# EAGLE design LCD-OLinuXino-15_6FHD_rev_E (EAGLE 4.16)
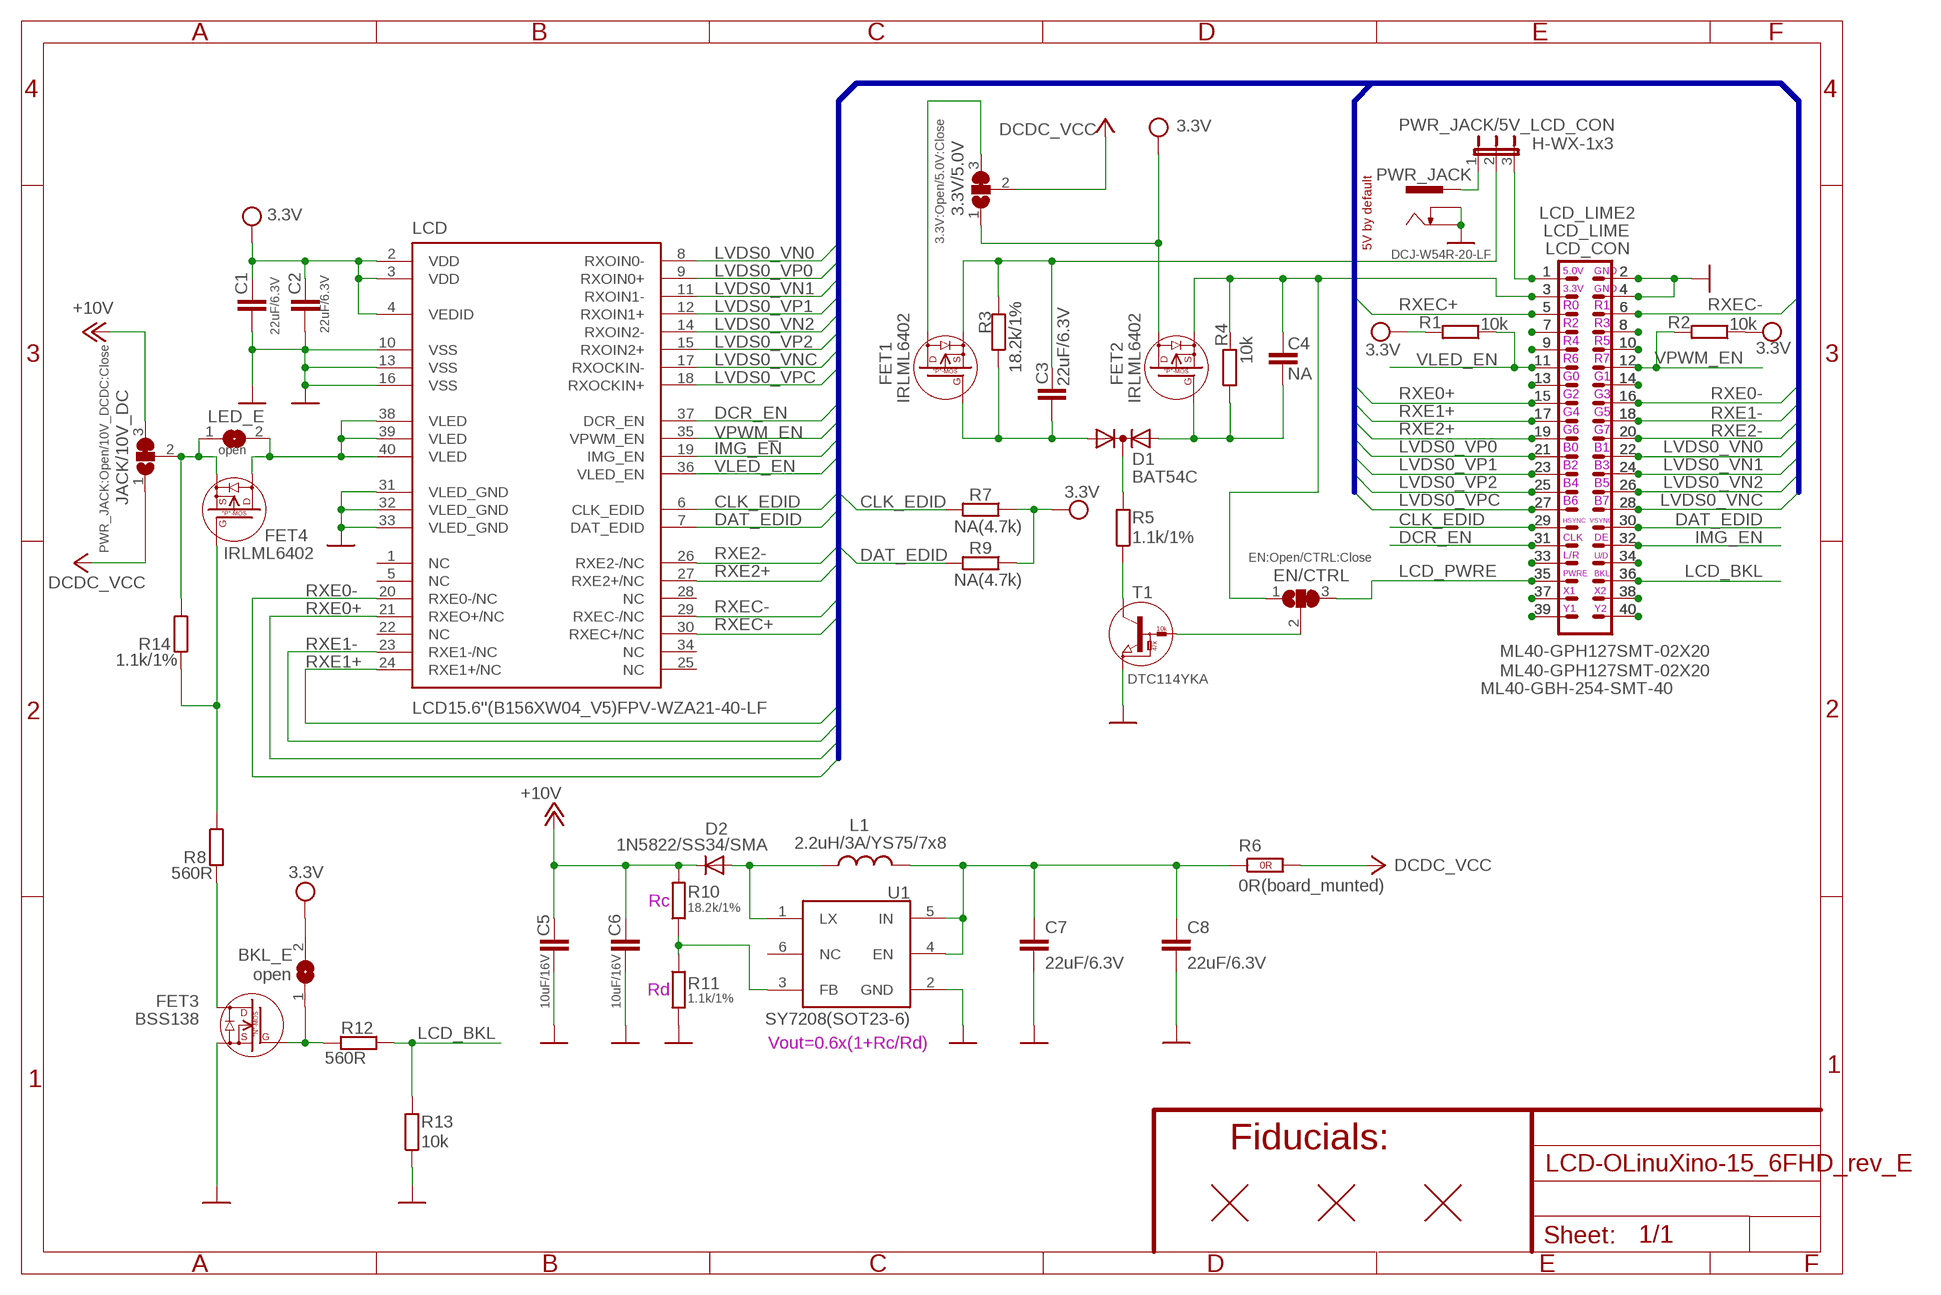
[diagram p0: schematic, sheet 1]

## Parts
3.3V/5.0V  3.3V:Open/5.0V:Close  SJ2W5  [SJ_2_SMALL_23_TIED]
BKL_E  open  SJSJ_1_THE_SMALLEST  [SJ_1_THE_SMALLEST]
C1  22uF/6.3V  C-EUC0603_DWS  [C0603_DWS]
C2  22uF/6.3V  C-EUC0603_DWS  [C0603_DWS]
C3  22uF/6.3V  C-EUC0603_DWS  [C0603_DWS]
C4  NA  C-EUC0603_DWS  [C0603_DWS]
C5  10uF/16V  C-EUC0805_5MIL_DWS  [C0805_5MIL_DWS]
C6  10uF/16V  C-EUC0805_5MIL_DWS  [C0805_5MIL_DWS]
C7  22uF/6.3V  C-EUC0603_DWS  [C0603_DWS]
C8  22uF/6.3V  C-EUC0603_DWS  [C0603_DWS]
D1  BAT54C  DIODE_AC-CA_  [SOT23C]
D2  1N5822/SS34/SMA  D-MLL-41  [MELF-MLL41]
EN/CTRL  EN:Open/CTRL:Close  SJ2W5  [SJ_2_SMALL_23_TIED]
FET1  IRLML6402  P-MOS+DIODIRLML6402  [SOT23]
FET2  IRLML6402  P-MOS+DIODIRLML6402  [SOT23]
FET3  BSS138  N-MOS+DIODBSS138(SOT23-3)  [SOT23]
FET4  IRLML6402  P-MOS+DIODIRLML6402  [SOT23]
JACK/10V_DC  PWR_JACK:Open/10V_DCDC:Close  SJ2W3  [SJ_2_SMALL]
L1  2.2uH/3A/YS75/7x8  LLQH88PN100M38  [8X8MM_3131]
LCD  LCD15.6''(B156XW04_V5)FPV-WZA21-40-LF  [LCD_15.6'']
LCD_CON  ML40-GBH-254-SMT-40  [ML40-MALE(GBH-254-SMT-40)]
LCD_LIME  ML40-GPH127SMT-02X20  ML40YA-V36P-2X20-LF  [YA-V36P-2X20-LF]
LCD_LIME2  ML40-GPH127SMT-02X20  ML40-GPH127SMT-02X20(PA-V16X-2X20-LF)  [GPH127SMT-02X20(PA-V16X-2X20-LF)]
LED_E  open  SJSJ_1_THE_SMALLEST  [SJ_1_THE_SMALLEST]
PWR_JACK  DCJ-W54R-20-LF  PWR-JAKDCJ-W  [PWR-JACK-SMD]
PWR_JACK/5V_LCD_CON  H-WX-1x3  JP2EHN1X3-SMD  [HN1X3-SMD]
R1  10k  R-EU_R0603_5MIL_DWS  [R0603_5MIL_DWS]
R2  10k  R-EU_R0603_5MIL_DWS  [R0603_5MIL_DWS]
R3  18.2k/1%  R-EU_R0603_5MIL_DWS  [R0603_5MIL_DWS]
R4  10k  R-EU_R0603_5MIL_DWS  [R0603_5MIL_DWS]
R5  1.1k/1%  R-EU_R0603_5MIL_DWS  [R0603_5MIL_DWS]
R6  0R(board_munted)  R_0R0R(NA)  [0603_0R]
R7  NA(4.7k)  R-EU_R0603_5MIL_DWS  [R0603_5MIL_DWS]
R8  560R  R-EU_R0603_5MIL_DWS  [R0603_5MIL_DWS]
R9  NA(4.7k)  R-EU_R0603_5MIL_DWS  [R0603_5MIL_DWS]
R10  18.2k/1%  R-EU_R0603_5MIL_DWS  [R0603_5MIL_DWS]
R11  1.1k/1%  R-EU_R0603_5MIL_DWS  [R0603_5MIL_DWS]
R12  560R  R-EU_R0603_5MIL_DWS  [R0603_5MIL_DWS]
R13  10k  R-EU_R0603_5MIL_DWS  [R0603_5MIL_DWS]
R14  1.1k/1%  R-EU_R0603_5MIL_DWS  [R0603_5MIL_DWS]
T1  DTC114YKA  DIGITAL_TRANSISTORS-NPNDTC114YKA  [SOT-23]
U1  SY7208(SOT23-6)  SY7208  [SOT23-6]
U$1  FIDUCIAL  [FIDUCIAL-1X3]
U$2  FIDUCIAL  [FIDUCIAL-1X3]
U$3  FIDUCIAL  [FIDUCIAL-1X3]

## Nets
3.3VDC [pwr]: C4.1 EN/CTRL.1 FET2.2(S) LCD_CON.3 LCD_LIME2.3 LCD_LIME.3 R4.2
5VDC: C3.1 FET1.2(S) PWR_JACK/5V_LCD_CON.2 R3.2
+5V: 3.3V/5.0V.2 JACK/10V_DC.1 R6.2(1.2) ; supply symbol labelled DCDC_VCC
+12V [pwr]: C5.1 C6.1 D2.1(C) JACK/10V_DC.3 R10.2 ; supply symbol labelled +10V
CLK_EDID: LCD.6(CLK_EDID) LCD_CON.29 LCD_LIME2.29 LCD_LIME.29 R7.2
DAT_EDID: LCD.7(DAT_EDID) LCD_CON.30 LCD_LIME2.30 LCD_LIME.30 R9.2
DCR_EN: LCD.37(DCR_EN) LCD_CON.31 LCD_LIME2.31 LCD_LIME.31
GND [pwr]: C1.2 C2.2 C5.2 C6.2 C7.2 C8.2 FET3.2(S) LCD.10(VSS) LCD.13(VSS) LCD.16(VSS) LCD.31(VLED_GND) LCD.32(VLED_GND) LCD.33(VLED_GND) LCD_CON.2 LCD_CON.4 LCD_LIME2.2 LCD_LIME2.4 LCD_LIME.2 LCD_LIME.4 PWR_JACK.2(-) PWR_JACK.3(--) R11.2 R13.1 T1.2(E) U1.2(GND)
IMG_EN: LCD.19(IMG_EN) LCD_CON.32 LCD_LIME2.32 LCD_LIME.32
LCD_BKL: LCD_CON.36 LCD_LIME2.36 LCD_LIME.36 R12.1 R13.2
LCD_PWRE: EN/CTRL.3 LCD_CON.35 LCD_LIME2.35 LCD_LIME.35
LVDS0_VN0: LCD.8(RXOIN0-) LCD_CON.22 LCD_LIME2.22 LCD_LIME.22
LVDS0_VN1: LCD.11(RXOIN1-) LCD_CON.24 LCD_LIME2.24 LCD_LIME.24
LVDS0_VN2: LCD.14(RXOIN2-) LCD_CON.26 LCD_LIME2.26 LCD_LIME.26
LVDS0_VNC: LCD.17(RXOCKIN-) LCD_CON.28 LCD_LIME2.28 LCD_LIME.28
LVDS0_VP0: LCD.9(RXOIN0+) LCD_CON.21 LCD_LIME2.21 LCD_LIME.21
LVDS0_VP1: LCD.12(RXOIN1+) LCD_CON.23 LCD_LIME2.23 LCD_LIME.23
LVDS0_VP2: LCD.15(RXOIN2+) LCD_CON.25 LCD_LIME2.25 LCD_LIME.25
LVDS0_VPC: LCD.18(RXOCKIN+) LCD_CON.27 LCD_LIME2.27 LCD_LIME.27
N$1: 3.3V/5.0V.3 FET1.3(D)
N$2 [pwr]: FET4.2(S) JACK/10V_DC.2 LED_E.1 R14.1
N$3 [pwr]: FET4.3(D) LCD.38(VLED) LCD.39(VLED) LCD.40(VLED) LED_E.2
N$4: BKL_E.1 FET3.1(G) R12.2
N$5: LCD_CON.7 LCD_LIME2.7 LCD_LIME.7
N$6: LCD_CON.9 LCD_LIME2.9 LCD_LIME.9
N$7: LCD_CON.13 LCD_LIME2.13 LCD_LIME.13
N$8: C4.2 D1.1(A1) FET2.1(G) R4.1
N$9: C3.2 D1.2(A2) FET1.1(G) R3.1
N$10: LCD_CON.33 LCD_LIME2.33 LCD_LIME.33
N$11: R5.1 T1.3(C)
N$12: LCD_CON.37 LCD_LIME2.37 LCD_LIME.37
N$13: LCD_CON.39 LCD_LIME2.39 LCD_LIME.39
N$14: LCD_CON.8 LCD_LIME2.8 LCD_LIME.8
N$15: LCD_CON.10 LCD_LIME2.10 LCD_LIME.10
N$16: EN/CTRL.2 T1.1(B)
N$17: LCD_CON.14 LCD_LIME2.14 LCD_LIME.14
N$18: LCD_CON.34 LCD_LIME2.34 LCD_LIME.34
N$19: D1.3(K) R5.2
N$20: LCD_CON.1 LCD_LIME2.1 LCD_LIME.1 PWR_JACK/5V_LCD_CON.3
N$21: LCD_CON.38 LCD_LIME2.38 LCD_LIME.38
N$22 [pwr]: PWR_JACK.1(+) PWR_JACK/5V_LCD_CON.1
N$23: LCD_CON.40 LCD_LIME2.40 LCD_LIME.40
N$24: C7.1 C8.1 L1.2 R6.1(1.1) U1.4(EN) U1.5(IN)
N$25: FET4.1(G) R8.1 R14.2
N$26: FET3.3(D) R8.2
N$123: D2.2(A) L1.1 U1.1(LX)
N$126: R10.1 R11.1 U1.3(FB)
RXE0+: LCD.21(RXEO+/NC) LCD_CON.15 LCD_LIME2.15 LCD_LIME.15
RXE0-: LCD.20(RXE0-/NC) LCD_CON.16 LCD_LIME2.16 LCD_LIME.16
RXE1+: LCD.24(RXE1+/NC) LCD_CON.17 LCD_LIME2.17 LCD_LIME.17
RXE1-: LCD.23(RXE1-/NC) LCD_CON.18 LCD_LIME2.18 LCD_LIME.18
RXE2+: LCD.27(RXE2+/NC) LCD_CON.19 LCD_LIME2.19 LCD_LIME.19
RXE2-: LCD.26(RXE2-/NC) LCD_CON.20 LCD_LIME2.20 LCD_LIME.20
RXEC+: LCD.30(RXEC+/NC) LCD_CON.5 LCD_LIME2.5 LCD_LIME.5
RXEC-: LCD.29(RXEC-/NC) LCD_CON.6 LCD_LIME2.6 LCD_LIME.6
VCC [pwr]: 3.3V/5.0V.1 BKL_E.2 C1.1 C2.1 FET2.3(D) LCD.2(VDD) LCD.3(VDD) LCD.4(VEDID) R1.2 R2.1 R7.1 R9.1 ; supply symbol labelled 3.3V
VLED_EN: LCD.36(VLED_EN) LCD_CON.11 LCD_LIME2.11 LCD_LIME.11 R1.1
VPWM_EN: LCD.35(VPWM_EN) LCD_CON.12 LCD_LIME2.12 LCD_LIME.12 R2.2
Unconnected: LCD.1(NC) LCD.5(NC) LCD.22(NC) LCD.25(NC) LCD.28(NC) LCD.34(NC) U1.6(NC)

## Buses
LVDS0_VP[0..2],LVDS0_VN[0..2],LVDS0_VPC,LVDS0_VNC,CLK_EDID,DAT_EDID,DCR_EN,IMG_EN,VPWM_EN,VLED_EN,RXE0-,RXE0+,RXE1-,RXE1+,RXE2-,RXE2+,RXEC-,RXEC+

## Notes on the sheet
- 5V by default
- 5.0V | GND
- 3.3V | GND
- R0 | R1
- R2 | R3
- R4 | R5
- R6 | R7
- G0 | G1
- G2 | G3
- G4 | G5
- G6 | G7
- B0 | B1
- B2 | B3
- B4 | B5
- B6 | B7
- HSYNC | VSYNC
- CLK | DE
- L/R | U/D
- PWRE | BKL
- X1 | X2
- Y1 | Y2
- Rc
- Rd
- Vout=0.6x(1+Rc/Rd)
- Fiducials:

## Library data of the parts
3.3V/5.0V EN/CTRL JACK/10V_DC = jumper:SJ2W: SMD solder JUMPER
BKL_E LED_E = jumper:SJ: SMD solder JUMPER
C1-C8 = rcl:C-EU: CAPACITOR, European symbol
D1 = semicon-smd-ipc:DIODE_AC-CA_: DUAL DIODE
D2 = semicon-smd-ipc:D-: DIODE
FET1 FET2 FET4 = Penko:P-MOS+DIOD
FET3 = Penko:N-MOS+DIOD
L1 = OLIMEX_DISCRET:L
LCD = olimex_lcd:LCD15.6''(B156XW04_V5): LCD B156XW04 V5 LCD type: Color Active Matrix Liquid Cristal Display composed of a TFT LCD panel, a driver circuit, and LED backlight system Screen format: 16x9 HD(1366x768 pixels) Number of colors: 262K colors(RGB 6-bits data driver) Pixel Pitch: 0.252x0.252mm Pixel Format: RGB Vertical Stripe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
LCD_CON LCD_LIME LCD_LIME2 = con-harting-ml:ML40: HARTING
PWR_JACK = gogo:PWR-JAK
PWR_JACK/5V_LCD_CON = jumper:JP2E: JUMPER
R1-R5 R7-R14 = rcl:R-EU_: RESISTOR, European symbol
R6 = OLIMEX_DISCRET:R_0R
T1 = OLIMEX_DISCRET:DIGITAL_TRANSISTORS-NPN: DTC114YKA Digital Transistor - NPN
U1 = OLIMEX_IC:SY7208
U$1-U$3 = SparkFunEagle-6-6-07:FIDUCIAL: Fiducial Alignment Points

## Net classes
1 pwr: width 0.254 mm, drill 0.241 mm, clearance 0.254 mm

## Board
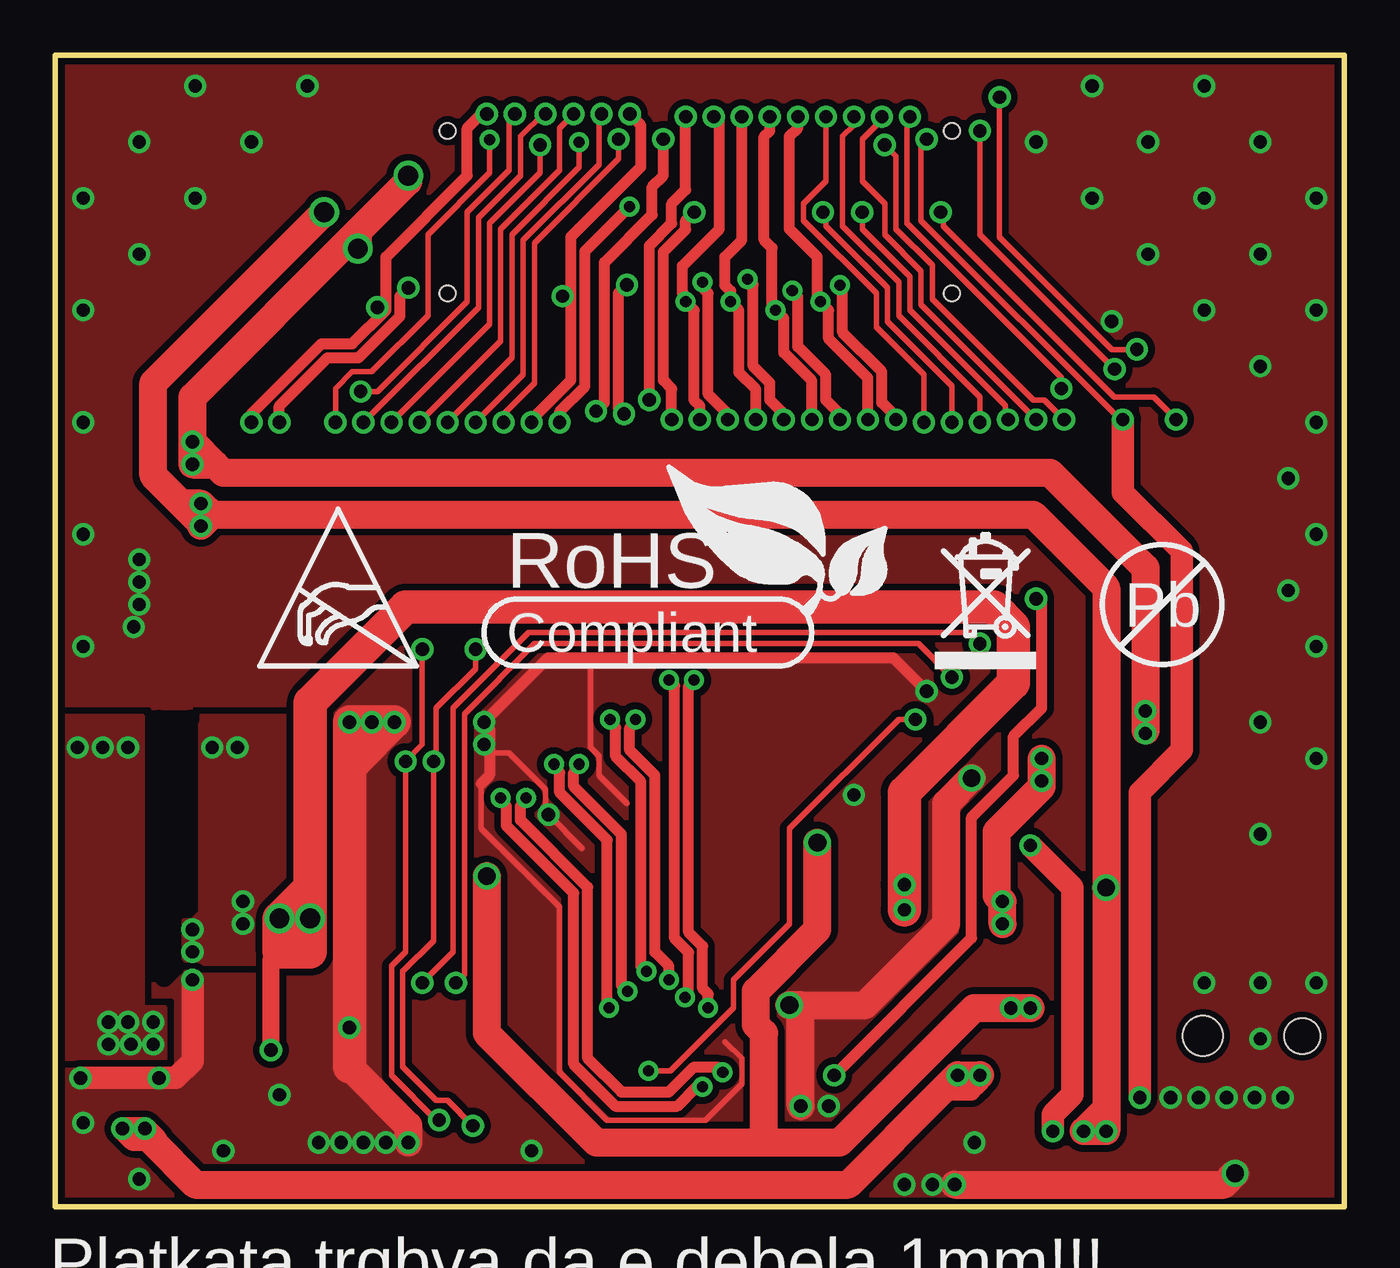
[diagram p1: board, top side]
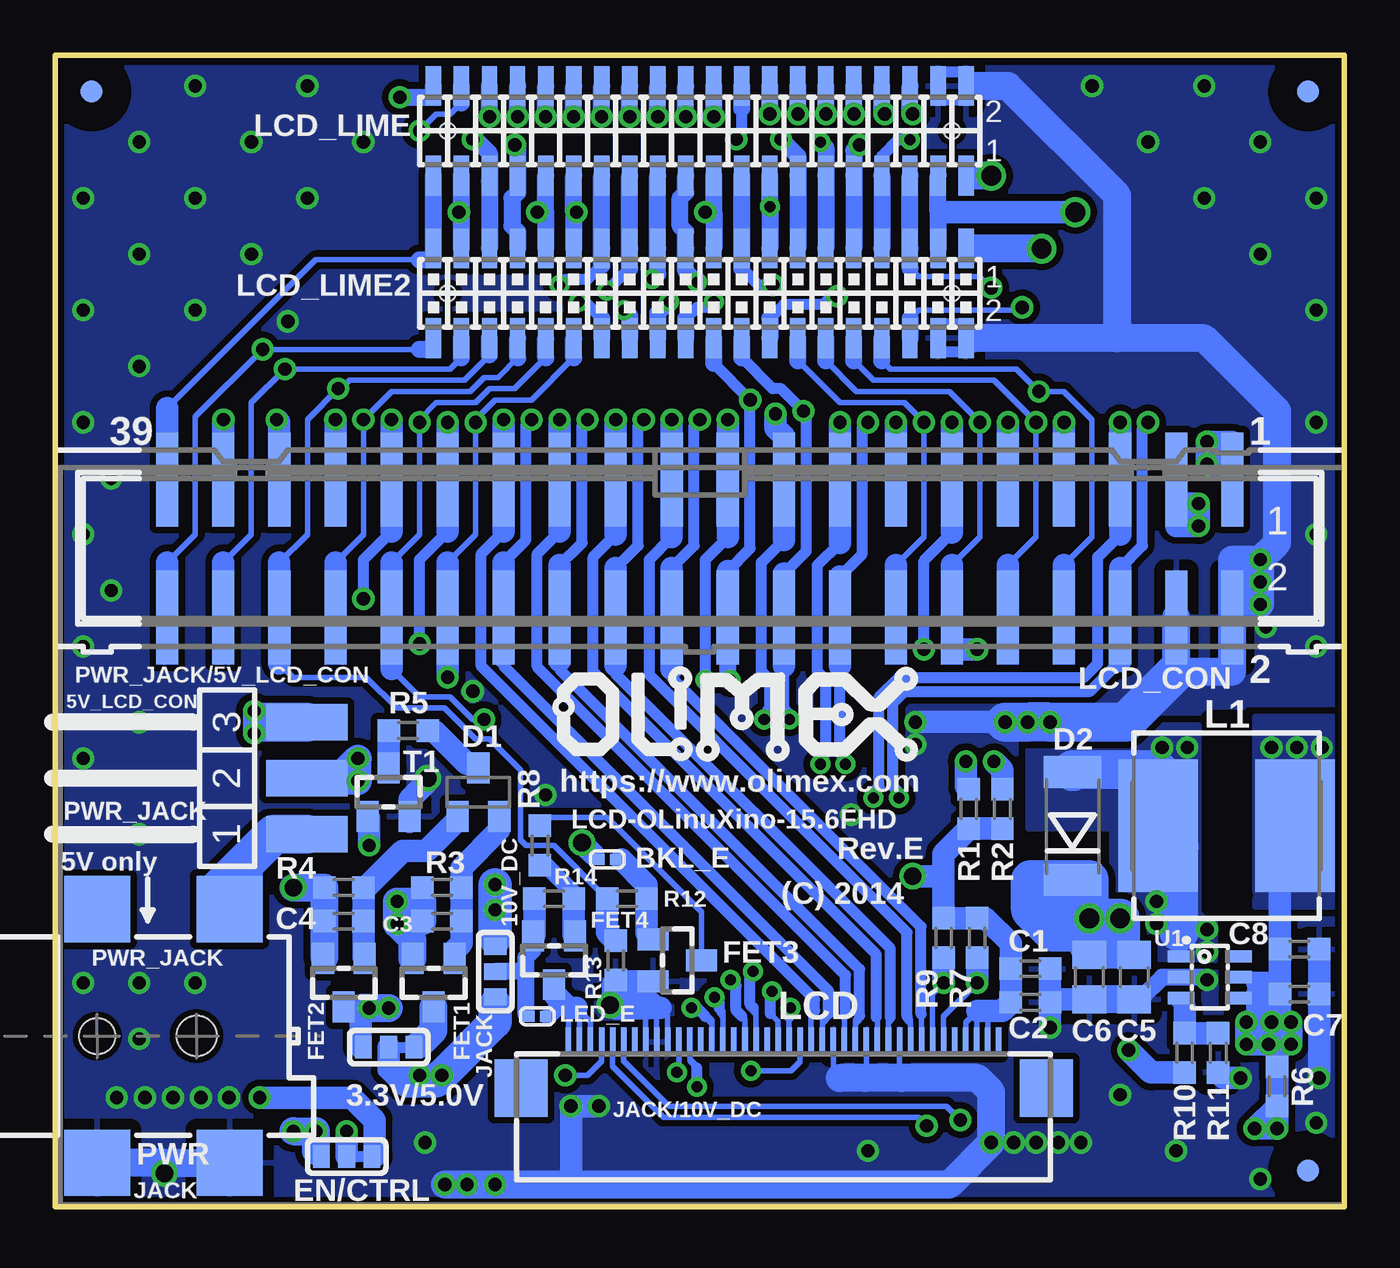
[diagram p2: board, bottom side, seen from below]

Size 58.42 x 52.2 mm. Coordinates in mm from the lower left corner, seen from the top.
Outline: 0,52.2 0,0 58.42,0 58.42,52.2 0,52.2
Copper layers (1+16): Top 0.035mm / dielectric 1mm / Bottom 0.035mm
Design rules "default": minimum track width 9.5mil, minimum drill 0.5mm, track to track 5mil, track to pad 5mil, pad to pad 5mil, via to via 5mil, smd to smd 1mil, copper to edge 10mil, drill to drill 8mil, minimum pad ring 8mil, minimum via ring 8mil, stop-mask expansion 4mil, vias tented up to drill 40mil, thermal gap 20mil
tRestrict: 3 lines
bRestrict: 2 lines

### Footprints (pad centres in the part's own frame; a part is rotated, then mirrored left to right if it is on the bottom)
SJ_2_SMALL_23_TIED = smd 0.762 x 1.016: 1 -1.143,0; 2 0,0; 3 1.143,0
SJ_1_THE_SMALLEST = smd 0.508 x 0.508: 1 -0.381,0; 2 0.381,0
C0603_DWS = smd 1.016 x 1.016: 1 -0.889,0; 2 0.889,0
C0805_5MIL_DWS = smd 1.27 x 1.524: 1 -1.016,0; 2 1.016,0
SOT23C = smd 1.4 x 1: 1 1.1,-0.95; 2 1.1,0.95; 3 -1.1,0
MELF-MLL41 = smd 1.45 x 2.6: 1 -2.445,0; 2 2.445,0
SOT23 = smd 1.4 x 1: 1 1.1,-0.95; 2 1.1,0.95; 3 -1.1,0
SJ_2_SMALL = smd 0.762 x 1.016: 1 -1.143,0; 2 0,0; 3 1.143,0
8X8MM_3131 = smd 3.6 x 6: 1 -3.1,0; 2 3.1,0
LCD_15.6'' = smd 0.25 x 1.3 bottom: 1 -67.54,31.89; 2 -67.04,31.89; 3 -66.54,31.89; 4 -66.04,31.89; 5 -65.54,31.89; 6 -65.04,31.89; 7 -64.54,31.89; 8 -64.04,31.89; 9 -63.54,31.89; 10 -63.04,31.89; 11 -62.54,31.89; 12 -62.04,31.89; 13 -61.54,31.89; 14 -61.04,31.89; 15 -60.54,31.89; 16 -60.04,31.89; 17 -59.54,31.89; 18 -59.04,31.89; 19 -58.54,31.89; 20 -58.04,31.89; 21 -57.54,31.89; 22 -57.04,31.89; 23 -56.54,31.89; 24 -56.04,31.89; 25 -55.54,31.89; 26 -55.04,31.89; 27 -54.54,31.89; 28 -54.04,31.89; 29 -53.54,31.89; 30 -53.04,31.89; 31 -52.54,31.89; 32 -52.04,31.89; 33 -51.54,31.89; 34 -51.04,31.89; 35 -50.54,31.89; 36 -50.04,31.89; 37 -49.54,31.89; 38 -49.04,31.89; 39 -48.54,31.89; 40 -48.04,31.89 | smd 2.4 x 2.6 bottom: P1 -69.69,29.79; P2 -45.89,29.79
ML40-MALE(GBH-254-SMT-40) = smd 1 x 4.25: 1 -24.13,-3.125; 2 -24.13,3.125; 3 -21.59,-3.125; 4 -21.59,3.125; 5 -19.05,-3.125; 6 -19.05,3.125; 7 -16.51,-3.125; 8 -16.51,3.125; 9 -13.97,-3.125; 10 -13.97,3.125; 11 -11.43,-3.125; 12 -11.43,3.125; 13 -8.89,-3.125; 14 -8.89,3.125; 15 -6.35,-3.125; 16 -6.35,3.125; 17 -3.81,-3.125; 18 -3.81,3.125; 19 -1.27,-3.125; 20 -1.27,3.125; 21 1.27,-3.125; 22 1.27,3.125; 23 3.81,-3.125; 24 3.81,3.125; 25 6.35,-3.125; 26 6.35,3.125; 27 8.89,-3.125; 28 8.89,3.125; 29 11.43,-3.125; 30 11.43,3.125; 31 13.97,-3.125; 32 13.97,3.125; 33 16.51,-3.125; 34 16.51,3.125; 35 19.05,-3.125; 36 19.05,3.125; 37 21.59,-3.125; 38 21.59,3.125; 39 24.13,-3.125; 40 24.13,3.125
YA-V36P-2X20-LF = smd 0.7 x 1.8: 1 -12.065,2.032; 2 -12.065,-2.032; 3 -10.795,2.032; 4 -10.795,-2.032; 5 -9.525,2.032; 6 -9.525,-2.032; 7 -8.255,2.032; 8 -8.255,-2.032; 9 -6.985,2.032; 10 -6.985,-2.032; 11 -5.715,2.032; 12 -5.715,-2.032; 13 -4.445,2.032; 14 -4.445,-2.032; 15 -3.175,2.032; 16 -3.175,-2.032; 17 -1.905,2.032; 18 -1.905,-2.032; 19 -0.635,2.032; 20 -0.635,-2.032; 21 0.635,2.032; 22 0.635,-2.032; 23 1.905,2.032; 24 1.905,-2.032; 25 3.175,2.032; 26 3.175,-2.032; 27 4.445,2.032; 28 4.445,-2.032; 29 5.715,2.032; 30 5.715,-2.032; 31 6.985,2.032; 32 6.985,-2.032; 33 8.255,2.032; 34 8.255,-2.032; 35 9.525,2.032; 36 9.525,-2.032; 37 10.795,2.032; 38 10.795,-2.032; 39 12.065,2.032; 40 12.065,-2.032 | hole 0.7: -11.43,0; 11.43,0
GPH127SMT-02X20(PA-V16X-2X20-LF) = smd 0.7 x 1.8: 1 -12.065,-2.032; 2 -12.065,2.032; 3 -10.795,-2.032; 4 -10.795,2.032; 5 -9.525,-2.032; 6 -9.525,2.032; 7 -8.255,-2.032; 8 -8.255,2.032; 9 -6.985,-2.032; 10 -6.985,2.032; 11 -5.715,-2.032; 12 -5.715,2.032; 13 -4.445,-2.032; 14 -4.445,2.032; 15 -3.175,-2.032; 16 -3.175,2.032; 17 -1.905,-2.032; 18 -1.905,2.032; 19 -0.635,-2.032; 20 -0.635,2.032; 21 0.635,-2.032; 22 0.635,2.032; 23 1.905,-2.032; 24 1.905,2.032; 25 3.175,-2.032; 26 3.175,2.032; 27 4.445,-2.032; 28 4.445,2.032; 29 5.715,-2.032; 30 5.715,2.032; 31 6.985,-2.032; 32 6.985,2.032; 33 8.255,-2.032; 34 8.255,2.032; 35 9.525,-2.032; 36 9.525,2.032; 37 10.795,-2.032; 38 10.795,2.032; 39 12.065,-2.032; 40 12.065,2.032 | hole 0.7: -11.43,0; 11.43,0
PWR-JACK-SMD = smd 3 x 3: 1 6,5.75; 2 0,-5.75; 3 6,-5.75; 4 0,5.75 | hole 1.6: 0,0 | hole 1.8: 4.5,0
HN1X3-SMD = smd 1.651 x 3.683: 1 -2.54,-0.229; 2 0,-0.229; 3 2.54,-0.229
R0603_5MIL_DWS = smd 1.016 x 1.016: 1 -0.889,0; 2 0.889,0
0603_0R = smd 1.016 x 1.016: 1 -0.889,0; 2 0.889,0
SOT-23 = smd 1.4 x 1: 1 1.1,-0.95; 2 1.1,0.95; 3 -1.1,0
SOT23-6 = smd 1.2 x 0.55: 1 1.3,-0.95; 2 1.3,0; 3 1.3,0.95; 4 -1.3,0.95; 5 -1.3,0; 6 -1.3,-0.95
FIDUCIAL-1X3 = smd 1 x 1: 1 0,0

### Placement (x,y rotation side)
3.3V/5.0V  43.31,7.24 0 bottom
BKL_E  33.4,15.75 180 bottom
C1  14.22,10.79 0 bottom
C2  14.22,9.27 0 bottom
C3  40.89,12.95 0 bottom
C4  45.34,12.95 0 bottom
C5  9.53,10.41 270 bottom
C6  11.56,10.41 270 bottom
C7  2.03,9.65 0 bottom
C8  2.03,11.68 0 bottom
D1  39.24,18.8 270 bottom
D2  12.32,17.27 90 bottom
EN/CTRL  45.21,2.29 0 bottom
FET1  41.27,10.16 90 bottom
FET2  45.34,10.16 90 bottom
FET3  30.23,11.18 180 bottom
FET4  35.81,11.18 90 bottom
JACK/10V_DC  38.48,10.67 90 bottom
L1  5.33,17.27 0 bottom
LCD  83.2,-24.4 0 top
LCD_CON  29.21,29.84 180 bottom
LCD_LIME  29.21,48.77 180 bottom
LCD_LIME2  29.21,41.4 180 bottom
LED_E  36.58,8.64 0 bottom
PWR_JACK  56.52,7.75 0 bottom
PWR_JACK/5V_LCD_CON  47.24,19.43 90 bottom
R1  17.02,18.03 270 bottom
R2  15.49,18.03 90 bottom
R3  40.89,14.48 180 bottom
R4  45.34,14.48 180 bottom
R5  42.42,21.59 0 bottom
R6  3.05,5.46 270 bottom
R7  16.64,12.19 270 bottom
R8  36.45,16.38 90 bottom
R9  18.16,12.19 270 bottom
R10  7.24,6.99 270 bottom
R11  5.71,6.99 270 bottom
R12  32.51,13.97 0 bottom
R13  33.02,11.18 90 bottom
R14  35.81,13.97 0 bottom
T1  43.31,18.8 270 bottom
U1  6.1,10.41 180 bottom
U$1  56.77,50.55 270 bottom
U$2  1.65,1.65 270 bottom
U$3  1.65,50.55 270 bottom
U$5  [ROHS]  20.45,25.15 0 top
U$6  [PB]  50.16,27.3 0 top
U$8  [OLIMEX1_V]  18.16,20.07 0 bottom
U$10  [ESD_SYMBOL]  9.27,24.51 0 top
U$11  [RECYCLE_BIN1/8]  39.88,24.38 0 top

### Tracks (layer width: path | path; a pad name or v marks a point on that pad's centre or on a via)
3.3VDC  (via drill 0.6, 0.8, 0.9)
  Top 1.27: 7.11,31.37 v6.6,31.88 | v6.6,30.86 7.11,31.37 | v6.6,30.86 v6.6,31.88 | 7.11,31.37 44.32,31.37 47.62,28.07 v47.62,14.48 47.62,4.45 | 47.62,4.45 v47.62,3.43 v46.61,3.43 47.62,4.45 | v6.6,31.88 5.71,31.88 | 5.71,31.88 4.45,33.15 4.45,37.34 v12.19,45.09 | v6.6,30.86 6.6,30.99 5.71,31.88
  Bottom 0.508: 18.16,45.09 18.41,45.09
  Bottom 0.762: 46.61,2.54 EN/CTRL.1 | LCD_LIME2.3 18.41,45.09 LCD_LIME.3
  Bottom 1.016: 7.62,31.88 LCD_CON.3 | 7.62,31.88 v6.6,31.88 v6.6,30.86 7.62,30.86 7.62,31.88 | 46.23,11.32 FET2.2 | v12.19,45.09 18.16,45.09
  Bottom 1.27: 46.23,11.32 C4.1 R4.2 v47.62,14.48 | 46.61,2.54 v46.61,3.43 v47.62,3.43
5VDC  (via drill 0.6)
  Top 1.27: v44.7,20.32 v44.7,19.3 44.7,19.05 42.67,17.02 42.67,14.1 v42.93,13.84 v42.93,12.83
  Bottom 1.016: 41.78,13.84 R3.2
  Bottom 1.27: 45.72,19.3 v44.7,19.3 v44.7,20.32 45.72,19.3 | 45.72,19.3 46.89,19.3 PWR_JACK/5V_LCD_CON.2 | FET1.2 42.23,11.81 42.23,12.13 v42.93,12.83 v42.93,13.84 41.78,13.84 C3.1
+5V  (via drill 0.6)
  Top 0.762: v41.91,5.97 41.91,5.59 41.53,5.21 40.13,5.21
  Top 1.016: v4.06,3.56 4.57,3.05 4.32,3.05 3.56,3.05 v3.05,3.56 v4.06,3.56
  Top 1.27: v41.91,5.97 v40.89,5.97 40.13,5.21 35.94,1.02 6.35,1.02 4.32,3.05
  Bottom 0.508: 38.48,9.14 JACK/10V_DC.1 | v41.91,5.97 41.91,5.71
  Bottom 0.762: 42.55,5.71 42.95,5.71 43.43,6.2 43.43,7.11 3.3V/5.0V.2
  Bottom 1.016: 42.42,5.71 42.55,5.71 42.67,5.71 43.31,6.35 3.3V/5.0V.2 | R6.2 v3.05,3.56 v4.06,3.56 R6.2
  Bottom 1.524: 38.48,9.14 38.48,8.38 v40.89,5.97 41.15,5.71 41.91,5.71 42.42,5.71
+12V  (via drill 0.6, 0.9)
  Top 0.762: v9.78,7.11 9.78,11.18 10.16,11.56
  Top 1.524: v11.56,13.08 11.56,14.48 | v10.16,13.08 v11.56,13.08 | v10.16,13.08 11.56,14.48 | 11.56,14.48 11.56,22.86 15.88,27.18 42.55,27.18 43.43,26.29 43.43,23.75 38.48,18.8 v38.48,14.61 v38.48,13.46 | v11.56,13.08 11.56,11.56 10.16,11.56 v10.16,13.08
  Bottom 0.508: 38.48,12.19 JACK/10V_DC.3
  Bottom 1.016: R10.2 8.76,6.1 v9.78,7.11
  Bottom 1.27: 10.16,11.43 C5.1 | 10.16,11.43 C6.1 11.56,11.81 | 10.16,12.06 10.16,11.43
  Bottom 1.524: 38.48,12.19 v38.48,13.46 v38.48,14.61
  Bottom 1.778: 11.56,12.45 11.56,11.81 | v11.56,13.08 11.56,12.45 | v11.56,13.08 v10.16,13.08 10.16,12.06 | v11.56,13.08 11.56,14.83 D2.1 13.21,14.83 | 13.21,12.45 13.21,14.83 | 11.56,12.45 13.21,12.45 | 13.21,12.45 14.22,13.46 14.22,14.83 13.21,14.83
CLK_EDID  (via drill 0.6)
  Top 0.254: v16.64,10.16 18.03,11.56 18.03,22.61 21.46,26.04 41.4,26.04 v41.91,25.53 | v40.64,35.56 40.64,37.21 37.72,40.13 37.72,41.66 34.92,44.45 34.92,44.96 v34.8,45.09
  Bottom 0.254: LCD.6 18.16,8.64 v16.64,10.16
  Bottom 0.508: v41.91,25.53 41.91,29.34 40.64,30.61
  Bottom 0.762: 34.92,45.09 LCD_LIME2.29 | v34.8,45.09 34.92,45.09 | 34.92,45.09 LCD_LIME.29
  Bottom 1.016: 40.64,30.61 LCD_CON.29 v40.64,35.56 | v16.64,10.16 R7.2
DAT_EDID  (via drill 0.6)
  Top 0.254: v18.16,10.16 18.54,10.54 18.54,22.35 21.72,25.53 39.12,25.53 v40.64,24 | v39.37,35.56 39.37,37.72 37.21,39.88 37.21,41.4 33.91,44.7 33.91,45.47 34.92,46.48 v34.92,49.4
  Bottom 0.254: LCD.7 18.66,9.66 v18.16,10.16 | 40.64,29.21 39.37,30.48 v39.37,35.56 39.37,35.69 38.48,36.58 36.83,36.58 34.92,38.48
  Bottom 0.762: 34.92,38.48 LCD_LIME2.30 | v34.92,49.4 LCD_LIME.30
  Bottom 1.016: v40.64,24 LCD_CON.30 40.64,29.21 | v18.16,10.16 R9.2
DCR_EN  (via drill 0.6)
  Top 0.254: v43.18,35.69 43.05,35.81 43.05,36.32 38.73,40.64 38.73,42.16 36.58,44.32 v36.58,45.09
  Top 0.508: v35.31,5.97 41.53,12.19 41.53,17.65 43.43,19.56 43.43,21.34 44.7,22.61 44.7,27.3 v44.45,27.56
  Bottom 0.254: LCD.37 33.66,6.6 34.29,5.97 v35.31,5.97
  Bottom 0.508: v44.45,27.56 44.45,29.34 43.18,30.61
  Bottom 0.762: 36.2,45.09 LCD_LIME2.31 | 36.2,45.09 LCD_LIME.31 | v36.58,45.09 36.2,45.09
  Bottom 1.016: 43.18,30.61 LCD_CON.31 v43.18,35.69
GND  (via drill 0.6, 0.8)
  Top 0.254: 19.3,19.18 19.3,17.14 22.86,13.59 22.86,6.1 25.02,3.94 29.46,3.94 31.11,5.59 31.11,6.73 30.35,7.49 | 24.26,24.89 24.26,20.83 24.64,20.45 24.64,19.56 25.91,18.29 | 19.68,20.57 20.57,20.57 22.23,18.92 22.23,17.91 v22.35,17.78 23.88,16.26
  Top 0.508: 19.3,19.18 19.68,19.56 19.68,20.57 19.68,21.72 v19.43,21.97 22.35,24.89 24.26,24.89 37.97,24.89 v39.5,23.37
  Top 1.016: v6.22,10.29 6.22,6.6 5.46,5.84 v4.7,5.84 v1.14,5.84
  Top 1.27: 13.34,6.35 16,3.68 v16,2.92 | v41.53,19.43 40.39,18.29 40.39,12.83 36.7,9.14 33.78,9.14 | 33.78,9.14 v33.27,9.14 | v40.77,1.02 52.96,1.02 v53.47,1.52 | v33.78,4.57 33.78,9.14
  Top 1.524: 13.34,6.35 v13.34,8.13 13.34,20.19 | 13.34,20.19 v13.34,21.97 v14.35,21.97 v15.37,21.97 13.59,20.19 13.34,20.19
  Bottom 0.254: 20.07,5.84 20.07,5.97 20.16,6.06 LCD.10 | LCD.13 21.66,5.9 21.72,5.84 | LCD.16 23.16,6.14 22.86,5.84 | LCD.32 31.16,8.85 30.99,9.02 30.66,8.69 LCD.31 | LCD.33 31.66,8.73 31.37,9.02
  Bottom 0.508: LCD_LIME2.2 17.14,38.73 18.41,38.73 LCD_LIME2.4 18.41,40.01 17.14,40.01 LCD_LIME2.2 | 16.76,39.37 LCD_LIME2.2 | LCD_LIME.2 17.14,51.44 18.41,51.44 LCD_LIME.4 18.41,50.16 17.14,50.16 LCD_LIME.2 | 16.76,50.8 LCD_LIME.2
  Bottom 0.762: C5.2 9.27,9.4 8.26,10.41 U1.2 6.35,10.41 v6.22,10.29
  Bottom 1.016: 42.36,17.46 T1.2 42.36,18.48 41.53,19.3 v41.53,19.43 | v53.47,1.52 53.47,2 | v33.78,4.57 v35.05,4.57 35.05,1.02 | v13.34,8.13 C2.2 13.34,9.4 | C8.2 C7.2 v1.14,5.84 | 13.34,9.4 C1.2 | C6.2 13.34,9.4 | v15.37,21.97 v19.43,21.97 | v4.7,5.84 5.46,5.84 R11.2 | v33.27,9.14 33.15,9.14 33.15,10.1 33.02,10.23 | 33.02,10.23 R13.1 | 33.02,10.23 FET3.2 | 30.99,9.02 31.37,9.02 31.5,9.14
  Bottom 1.27: PWR_JACK.3 53.47,2 PWR_JACK.2 | v40.77,1.02 35.05,1.02 17.91,1.02 v16,2.92 16,5.21 16.64,5.84 20.07,5.84 21.72,5.84 22.86,5.84 | LCD_CON.4 7.62,24.26 5.08,24.26 LCD_CON.2 5.08,27.3 | C5.2 C6.2 | 16.76,50.8 15.24,50.8 10.29,45.85 10.29,39.37 | 10.29,39.37 16.76,39.37 | 10.29,39.37 6.35,39.37 3.05,36.07 3.05,30.1 v3.81,29.34 | 5.08,27.3 5.08,29.34 v3.81,29.34 | v3.81,29.34 v3.81,27.3 5.08,27.3 | 33.15,9.14 31.5,9.14
  Bottom 1.778: 7.62,24.26 9.91,21.97 v13.34,21.97 v14.35,21.97 v15.37,21.97
  other vias: 50.55,4.95 51.82,4.95 53.09,4.95 54.36,4.95 55.63,4.95 39.75,1.02 41.66,2.92 14.99,2.92 13.97,2.92 12.95,2.92 3.81,28.32 38.48,1.02 11.94,2.92 19.43,20.95 36.2,18.67 47.88,40.13 3.56,26.29 6.35,50.8 11.43,50.8 8.89,48.26 6.35,45.72 3.81,48.26 1.27,45.72 3.81,43.18 1.27,40.64 1.27,35.56 1.27,30.48 1.27,25.4 1.27,3.81 3.81,1.27 7.62,2.54 10.16,5.08 21.59,2.54 54.61,7.62 52.07,10.16 54.61,10.16 57.15,10.16 54.61,16.89 57.15,20.32 54.61,21.97 57.15,25.4 55.88,27.94 57.15,30.48 55.88,33.02 57.15,35.56 54.61,38.1 52.07,40.64 49.53,43.18 46.99,45.72 44.45,48.26 46.99,50.8 49.53,48.26 52.07,45.72 54.61,43.18 57.15,40.64 57.15,45.72 54.61,48.26 52.07,50.8
  pour Top (isolate 0.305, rank 2): 68.45,60.96 68.45,-5.08 -5.08,-5.08 -5.08,60.96
  pour Bottom (isolate 0.305, rank 3): -2.54,-2.54 64.26,-2.54 64.26,58.42 -2.54,58.42
IMG_EN  (via drill 0.5, 0.6)
  Top 0.254: v26.9,6.17 27.89,6.17 30.73,9.02 30.73,10.29 33.27,12.83 33.27,17.14 38.23,22.1 v38.99,22.1 | v41.91,35.56 41.91,36.7 38.23,40.39 38.23,41.91 35.69,44.45 35.69,48.51 36.2,49.02 v36.2,49.4
  Bottom 0.254: LCD.19 24.66,6.58 25.07,6.17 v26.9,6.17 | 43.18,24.38 41.91,23.11 40.51,23.11 39.5,22.1 v38.99,22.1 | 43.18,29.21 41.91,30.48 v41.91,35.56 41.91,35.69 41.15,36.45 39.37,36.45 38.73,37.08 37.59,37.08 36.2,38.48
  Bottom 0.762: 36.2,38.48 LCD_LIME2.32 | v36.2,49.4 LCD_LIME.32
  Bottom 1.016: 43.18,24.38 LCD_CON.32 43.18,29.21
LCD_BKL  (via drill 0.6)
  Top 0.254: v45.59,37.08 45.59,37.59 38.61,44.58 38.61,49.28 v38.73,49.4
  Bottom 0.254: 48.26,24.64 47.62,24 44.32,24 42.93,22.61 40.77,22.61 39.37,21.21 38.73,21.21 37.34,19.81 37.34,16.64 37.08,16.38 35.81,16.38 R12.1 | 48.26,29.21 46.99,30.48 46.99,35.69 v45.59,37.08 45.47,37.08 45.09,37.47 39.88,37.47 38.73,38.61
  Bottom 0.762: v38.73,49.4 LCD_LIME.36 | 38.73,38.61 LCD_LIME2.36
  Bottom 1.016: 48.26,24.64 LCD_CON.36 48.26,29.21 | R13.2 33.4,12.45 R12.1
LCD_PWRE  (via drill 0.6)
  Top 0.254: v48.39,35.69 48.26,35.69 39.24,44.7 39.24,48.13 v39.5,48.39
  Top 1.016: v49.15,4.95 49.15,18.8 51.05,20.7 51.05,29.72 48.39,32.38 v48.39,35.69
  Bottom 0.508: 38.73,46.48 LCD_LIME.35
  Bottom 0.762: EN/CTRL.3 43.94,2.29 | LCD_LIME2.35 38.73,46.48 38.73,47.75 39.37,48.39 v39.5,48.39
  Bottom 1.016: 43.94,2.29 43.94,3.94 44.96,4.95 v49.15,4.95 | v48.39,35.69 48.26,35.56 LCD_CON.35
LVDS0_VN0  (via drill 0.5, 0.6)
  Top 0.508: v29.21,35.69 29.21,36.3 28.96,36.55 28.96,40.64 v28.57,41.02 28.57,41.27 28.42,41.43 28.42,42.65 30.1,44.32 30.1,49.15 v29.84,49.4
  Bottom 0.254: LCD.8 19.16,8.72 19.18,8.74
  Bottom 0.508: 30.48,24.38 30.48,24 19.18,12.7 19.18,8.74 | 30.48,28.96 29.46,29.97 29.46,35.43 v29.21,35.69 | v28.57,41.02 28.83,40.77 29.34,40.77 29.84,40.26
  Bottom 0.762: 29.84,40.26 LCD_LIME2.22 | v29.84,49.4 LCD_LIME.22
  Bottom 1.016: 30.48,24.38 LCD_CON.22 30.48,28.96
LVDS0_VN1  (via drill 0.5, 0.6)
  Top 0.508: v31.75,35.69 31.75,37.06 30.99,37.82 30.99,40.64 v30.61,41.02 30.61,41.5 30.35,41.76 30.35,43.05 31.11,43.81 v31.11,49.4
  Bottom 0.254: LCD.11 20.66,8.34 | 20.66,8.34 20.66,8.53 20.57,8.61 20.57,8.42 20.66,8.34
  Bottom 0.508: 20.57,8.61 20.57,11.71 33.02,24.16 33.02,24.54 | 33.02,28.96 32,29.97 32,35.43 v31.75,35.69
  Bottom 0.762: v30.61,41.02 31.11,40.51 LCD_LIME2.24 | v31.11,49.4 LCD_LIME.24
  Bottom 1.016: 33.02,24.54 LCD_CON.24 33.02,28.96
LVDS0_VN2  (via drill 0.5, 0.6)
  Top 0.508: v34.29,35.69 34.29,37.44 33.02,38.71 33.02,40.26 v32.64,40.64 32.49,40.79 32.49,43.46 32.13,43.81 32.13,48.51 32.38,48.77 v32.38,49.4
  Bottom 0.254: LCD.14 22.16,8.29 | 22.16,8.29 22.16,8.47 21.97,8.66 21.97,8.48 22.16,8.29
  Bottom 0.508: 35.56,24.74 35.56,24.36 21.97,10.77 21.97,8.66 | 35.56,29.08 34.54,30.1 34.54,35.43 v34.29,35.69
  Bottom 0.762: v32.64,40.64 32.38,40.39 LCD_LIME2.26 | v32.38,49.4 LCD_LIME.26
  Bottom 1.016: 35.56,24.74 LCD_CON.26 35.56,29.08
LVDS0_VNC  (via drill 0.5, 0.6)
  Top 0.508: v36.83,35.69 36.83,37.57 35.05,39.34 35.05,40.64 v34.67,41.02 34.54,41.15 34.54,43.05 33.27,44.32 33.27,48.51 33.66,48.9 v33.66,49.4
  Bottom 0.254: LCD.17 23.66,8.35 | 23.66,8.35 23.66,8.47 23.37,8.76 23.37,8.59 23.61,8.35 23.66,8.35
  Bottom 0.508: 38.1,24.92 38.1,24.52 23.37,9.79 23.37,8.76 | 38.1,29.21 37.08,30.23 37.08,35.43 v36.83,35.69 | v34.67,41.02 34.42,41.02 33.66,40.26
  Bottom 0.762: 33.66,40.26 LCD_LIME2.28 | v33.66,49.4 LCD_LIME.28
  Bottom 1.016: 38.1,24.92 LCD_CON.28 38.1,29.21
LVDS0_VP0  (via drill 0.5, 0.6)
  Top 0.508: v30.48,35.69 30.48,35.94 29.59,36.83 29.59,41.4 29.34,41.66 v29.34,41.91
  Bottom 0.254: LCD.9 19.66,8.31 | 19.66,8.31 19.66,8.48 19.81,8.64 19.81,8.46 19.66,8.31
  Bottom 0.508: 30.48,30.35 31.5,29.34 31.5,24.12 19.81,12.43 19.81,8.64
  Bottom 0.762: LCD_LIME.21 29.84,45.97 30.1,45.72 30.1,44.45 29.84,44.2 LCD_LIME2.21 29.84,42.42 v29.34,41.91
  Bottom 1.016: 30.48,30.35 LCD_CON.21 v30.48,35.69
LVDS0_VP1  (via drill 0.5, 0.6)
  Top 0.508: v33.02,35.69 33.02,35.94 32.38,36.58 32.38,37.34 31.62,38.1 31.62,41.78 v31.37,42.04
  Bottom 0.254: LCD.12 21.16,8.56 21.21,8.61
  Bottom 0.508: 33.02,30.48 34.04,29.46 34.04,24.27 21.21,11.44 21.21,8.61
  Bottom 0.762: LCD_LIME.23 LCD_LIME2.23 31.11,42.29 v31.37,42.04
  Bottom 1.016: 33.02,30.48 LCD_CON.23 v33.02,35.69
LVDS0_VP2  (via drill 0.5, 0.6)
  Top 0.508: v35.56,35.69 35.56,35.94 34.92,36.58 34.92,37.72 33.66,38.99 33.66,41.27 v33.4,41.53
  Bottom 0.254: LCD.15 22.66,8.53 | 22.66,8.53 22.66,8.71 22.61,8.76 22.61,8.58 22.66,8.53
  Bottom 0.508: 35.56,30.61 36.58,29.59 36.58,24.47 22.61,10.5 22.61,8.76 | v33.4,41.53 32.38,42.55
  Bottom 0.762: LCD_LIME.25 LCD_LIME2.25 32.38,42.55
  Bottom 1.016: 35.56,30.61 LCD_CON.25 v35.56,35.69
LVDS0_VPC  (via drill 0.5, 0.6)
  Top 0.508: v38.1,35.69 38.1,35.81 37.47,36.45 37.47,37.85 35.69,39.62 35.69,41.66 v35.56,41.78
  Bottom 0.254: LCD.18 24.16,8.56 | 24.16,8.56 24.16,8.73 24,8.89 24,8.71 24.16,8.56
  Bottom 0.508: 38.1,30.61 39.12,29.59 39.12,24.51 24,9.4 24,8.89 | v35.56,41.78 35.31,42.04 34.29,42.04 33.66,42.67
  Bottom 0.762: LCD_LIME.27 LCD_LIME2.27 33.66,42.67
  Bottom 1.016: 38.1,30.61 LCD_CON.27 v38.1,35.69
N$1
  Bottom 0.762: 41.91,7.37 42.04,7.24 3.3V/5.0V.3
  Bottom 1.27: FET1.3 41.27,8 41.91,7.37
N$2
  Bottom 0.508: LED_E.1 37.08,8.76
  Bottom 0.762: FET4.2 36.76,11.62 37.08,11.3 37.08,10.67 | 37.08,10.67 JACK/10V_DC.2 | 37.08,8.76 37.08,10.67
  Bottom 1.016: FET4.2 36.7,12.34 R14.1
N$3
  Bottom 0.254: LCD.38 34.16,8.38 34.66,8.88 | LCD.40 35.16,8.65 34.8,9.02 34.66,8.88 | LCD.39 34.66,8.88
  Bottom 0.508: 36.07,8.64 LED_E.2
  Bottom 0.762: 35.43,9.27 36.07,8.64
  Bottom 1.016: 34.8,9.02 35.18,9.02 35.43,9.27 35.81,9.65 FET4.3
N$4
  Bottom 0.508: 32.77,15.75 BKL_E.1
  Bottom 1.016: 32.77,15.75 31.62,14.61 R12.2 31.62,12.42 FET3.1
N$5  (via drill 0.5, 0.6)
  Top 0.254: v19.68,48.36 19.68,46.86 16.89,44.07 16.89,40.39 14.35,37.85 13.46,37.85 12.7,37.08 v12.7,35.56
  Bottom 0.508: LCD_LIME.7 20.95,47.62 20.22,48.36 v19.68,48.36
  Bottom 0.762: LCD_LIME.7 LCD_LIME2.7
  Bottom 1.016: LCD_CON.7 v12.7,35.56
N$6  (via drill 0.6)
  Top 0.254: v21.97,48.13 21.97,46.86 19.68,44.58 19.68,40.01 v15.24,35.56
  Bottom 0.762: LCD_LIME2.9 LCD_LIME.9 22.23,47.88 v21.97,48.13
  Bottom 1.016: LCD_CON.9 v15.24,35.56
N$7  (via drill 0.6)
  Top 0.254: v20.32,35.56 20.32,35.94 21.72,37.34 21.72,43.69 25.53,47.5 v25.53,48.39
  Bottom 0.762: LCD_LIME2.13 LCD_LIME.13 24.77,47.62 v25.53,48.39
  Bottom 1.016: LCD_CON.13 v20.32,35.56
N$8
  Bottom 1.016: D1.1 40.19,17.53 41.59,16.13 42.67,16.13 44.32,14.48 R4.1 C4.2 44.45,11.32 FET2.1
N$9
  Bottom 1.016: FET1.1 40.33,11.62 40.01,11.94 C3.2 R3.1 40.01,15.37 38.29,17.08 D1.2
N$10  (via drill 0.6)
  Top 0.254: v45.72,35.69 44.83,36.58 44.32,36.58 39.75,41.15 39.75,42.67 38.1,44.32 38.1,47.62 v37.59,48.13
  Bottom 0.762: LCD_LIME2.33 37.47,44.2 37.72,44.45 37.72,45.72 37.47,45.97 LCD_LIME.33 37.47,48.01 v37.59,48.13
  Bottom 1.016: LCD_CON.33 v45.72,35.69
N$11
  Bottom 1.016: T1.3 R5.1
N$12  (via drill 0.6)
  Top 0.254: v40.13,45.09 40.26,44.96 40.26,44.45 48.01,36.7 49.78,36.7 v50.8,35.69
  Bottom 0.762: LCD_LIME2.37 40.01,45.21 | 40.01,45.21 v40.13,45.09 | 40.01,45.21 LCD_LIME.37
  Bottom 1.016: v50.8,35.69 LCD_CON.37
N$13
  Bottom 0.254: 41.91,42.93 46.61,42.93 53.34,36.2
  Bottom 0.762: 41.91,42.93 41.27,42.93 LCD_LIME2.39 LCD_LIME.39
  Bottom 1.016: 53.34,36.2 LCD_CON.39
N$14  (via drill 0.6)
  Top 0.254: v13.84,36.96 14.61,36.96 18.67,41.02 18.67,45.09 20.57,46.99 20.57,49.28 v20.83,49.53
  Bottom 0.254: 20.95,38.35 20.57,37.97 14.86,37.97 v13.84,36.96 12.7,36.96 11.43,35.69 11.43,30.35 12.7,29.08
  Bottom 0.762: 20.95,38.35 LCD_LIME2.8 | v20.83,49.53 20.95,49.66 LCD_LIME.8
  Bottom 1.016: LCD_CON.8 12.7,29.08
N$15  (via drill 0.6)
  Top 0.254: v13.97,35.56 19.18,40.77 19.18,44.83 21.08,46.74 21.08,48.51 22.1,49.53 v22.23,49.53
  Bottom 0.254: 22.23,38.35 21.34,37.47 15.88,37.47 v13.97,35.56 13.97,30.35 15.24,29.08
  Bottom 0.762: 22.23,38.35 LCD_LIME2.10 | v22.23,49.53 LCD_LIME.10
  Bottom 1.016: LCD_CON.10 15.24,29.08
N$16  (via drill 0.6)
  Top 1.016: v45.21,3.43 45.21,4.19 46.1,5.08 46.1,14.48 v44.2,16.38
  Bottom 1.016: v44.2,16.38 44.2,17.64 T1.1 | EN/CTRL.2 v45.21,3.43
N$17  (via drill 0.6)
  Top 0.254: v19.05,35.56 21.21,37.72 21.21,43.81 24.64,47.24 24.64,49.4 v24.77,49.53
  Bottom 0.254: 24.77,38.35 22.86,36.45 19.94,36.45 v19.05,35.56 19.05,30.35 20.32,29.08
  Bottom 0.762: 24.77,38.35 LCD_LIME2.14 | v24.77,49.53 LCD_LIME.14
  Bottom 1.016: LCD_CON.14 20.32,29.08
N$18  (via drill 0.6)
  Top 0.254: v44.45,35.69 39.24,40.89 39.24,42.42 37.59,44.07 37.59,45.47 36.58,46.48 36.58,48.39 37.47,49.28 v37.47,49.4
  Bottom 0.254: 45.72,29.21 44.45,30.48 v44.45,35.69 43.18,36.96 39.62,36.96 38.99,37.59 38.35,37.59 37.47,38.48
  Bottom 0.762: v37.47,49.4 LCD_LIME.34 | 37.47,38.48 LCD_LIME2.34
  Bottom 1.016: LCD_CON.34 45.72,29.21
N$19
  Bottom 1.016: D1.3 39.41,20.07 39.75,20.07 41.27,21.59 R5.2
N$20  (via drill 0.6, 0.9)
  Top 1.016: v49.4,21.46 49.4,21.59 v49.4,22.48
  Top 1.27: 49.4,21.59 49.4,28.96 45.09,33.27 7.62,33.27 7.24,33.66 | v6.22,34.67 7.24,33.66 | v6.22,34.67 v6.22,33.66 7.24,33.66 | 13.72,44.2 16,46.48 v16,46.74 | 13.72,44.2 v13.72,43.43 | v6.22,34.67 6.22,36.7 13.72,44.2
  Bottom 0.508: 16.76,43.43 LCD_LIME2.1 | 16.76,46.74 LCD_LIME.1
  Bottom 1.016: 5.08,33.66 5.08,34.67 v6.22,34.67 v6.22,33.66 5.08,33.66 | LCD_CON.1 5.08,33.66 | v49.4,21.46 49.4,21.97 | 49.4,21.97 49.02,21.97 | v49.4,22.48 49.4,21.97
  Bottom 1.27: v16,46.74 16.76,46.74 | v13.72,43.43 16.76,43.43
  Bottom 1.778: 49.02,21.97 PWR_JACK/5V_LCD_CON.3
N$21  (via drill 0.6)
  Top 0.254: v41.91,48.77 41.91,44.07 v48.01,37.97
  Bottom 0.254: 50.8,29.21 49.53,30.48 49.53,36.45 v48.01,37.97 40.51,37.97 40.01,38.48 | v41.91,48.77 41.15,49.53 40.51,49.53 40.01,50.04
  Bottom 0.762: 40.01,50.04 LCD_LIME.38 | 40.01,38.48 LCD_LIME2.38
  Bottom 1.016: 50.8,29.21 LCD_CON.38
N$22
  Bottom 1.778: PWR_JACK.1 49.91,14.1 49.91,15.49 50.29,15.11 | PWR_JACK/5V_LCD_CON.1 48.51,16.89 50.29,15.11 | 50.29,15.11 51.05,14.35
N$23  (via drill 0.6)
  Top 0.254: v49.02,38.86 47.88,38.86 42.8,43.94 v42.8,50.29
  Bottom 0.254: 53.34,29.21 52.07,30.48 52.07,35.81 v49.02,38.86 41.91,38.86
  Bottom 0.508: LCD_LIME2.40 41.27,38.86 41.53,38.86
  Bottom 0.762: v42.8,50.29 41.27,50.29 LCD_LIME.40 | 41.53,38.86 41.91,38.86
  Bottom 1.016: 53.34,29.21 LCD_CON.40
N$24  (via drill 0.6)
  Bottom 0.508: U1.5 3.94,10.41 3.94,10.16 3.94,9.65 3.94,9.46 U1.4
  Bottom 0.813: C7.1 2.92,10.16
  Bottom 1.016: L1.2 2.92,16.59 C8.1 2.92,10.16 3.94,10.16 | 2.92,8.38 v3.3,8.38 3.94,8.38 | 2.92,8.38 v2.41,8.38 v2.41,7.37 3.05,7.37 | 2.92,8.38 C7.1 3.94,9.65 3.94,8.38 | 3.94,8.38 v4.45,8.38 v4.45,7.37 v3.43,7.37 3.05,7.37 | 3.05,7.37 R6.1 3.05,4.7
  other vias: 1.02,20.83 2.16,20.83 3.3,20.83
  pour Top (isolate 0.305): 3.94,22.23 0.51,22.23 0.51,6.73 4.95,6.73 4.95,9.02 3.94,9.02
  pour Bottom (isolate 0.305, no thermals): 0.51,22.23 4.06,22.23 4.06,13.59 0.51,13.59
N$25
  Bottom 0.762: R8.1 36.2,15.49 34.92,14.22 R14.2
  Bottom 1.016: FET4.1 34.92,12.34 R14.2
N$26
  Bottom 0.254: FET3.3 29.13,13.38 33.4,17.65 36.07,17.65 R8.2
N$123  (via drill 0.6)
  Bottom 0.508: U1.1 7.49,11.36 7.49,12.45
  Bottom 1.778: 7.49,12.45 7.49,16.33 L1.1 8.43,19.81 12.32,19.81 D2.2
  other vias: 6.22,11.56 6.22,12.57 8.51,12.83 8.51,13.84 7.11,20.83 8.26,20.83
  pour Top (isolate 0.305, no thermals): 6.6,22.23 6.6,13.34 6.22,12.95 5.84,12.95 5.84,11.05 10.41,11.05 10.41,22.23
  pour Bottom (isolate 0.305, no thermals): 10.54,21.84 10.54,21.08 14.35,21.08 14.35,17.14 10.54,17.14 10.54,11.18 5.84,11.18 5.84,13.08 6.35,13.08 6.6,13.34 6.6,21.84
N$126
  Bottom 0.508: U1.3 7.24,9.46 7.24,9.02 7.34,9.02 7.72,9.4
  Bottom 1.016: R11.1 R10.1 7.24,9.02
RXE0+  (via drill 0.5, 0.6)
  Top 0.508: v25.93,9.77 25.65,10.05 25.65,16.89 23.5,19.05 23.5,19.68 23.75,19.94 v23.75,20.07 | v22.86,35.56 22.86,36.04 24,37.19 24,43.31 v26.04,45.34
  Bottom 0.254: LCD.21 25.66,8.41 26.01,8.76
  Bottom 0.508: 26.01,8.76 26.01,9.69 v25.93,9.77 | v23.75,20.07 23.75,20.32 23.5,20.57 23.5,23.89 23.88,24.27 23.88,29.08 22.86,30.1
  Bottom 0.762: LCD_LIME.15 v26.04,45.34 LCD_LIME2.15
  Bottom 1.016: 22.86,30.1 LCD_CON.15 v22.86,35.56
RXE0-  (via drill 0.5, 0.6)
  Top 0.508: v25.09,9.02 25.02,9.09 25.02,16.62 22.86,18.78 22.86,19.68 22.61,19.94 v22.61,20.07 | v21.59,35.56 21.59,35.69 23.37,37.47 23.37,41.27 | v26.04,49.53 26.54,49.02 26.54,47.14 23.37,43.97 23.37,41.27 | 23.37,41.27 v22.99,41.27
  Bottom 0.254: LCD.20 25.16,8.64 25.15,8.64
  Bottom 0.508: v25.09,9.02 25.15,9.02 25.15,8.64 | v22.61,20.07 22.61,20.32 22.86,20.57 22.86,24.51 | 22.86,28.57 21.84,29.59 21.84,35.31 v21.59,35.56 | v22.99,41.27 23.24,41.27 23.62,40.89 25.4,40.89 26.04,40.26
  Bottom 0.762: 26.04,40.26 LCD_LIME2.16 | v26.04,49.53 LCD_LIME.16
  Bottom 1.016: 22.86,24.51 LCD_CON.16 22.86,28.57
RXE1+  (via drill 0.5, 0.6)
  Top 0.508: v27.81,10.29 27.81,10.92 27.18,11.56 27.18,19.56 26.04,20.7 26.04,21.72 26.29,21.97 v26.29,22.1 | v25.78,35.94 25.53,36.2 25.53,41.4 v25.91,41.78
  Bottom 0.254: LCD.24 27.16,8.5 27.3,8.65
  Bottom 0.508: 27.3,8.65 27.56,8.9 27.56,10.03 v27.81,10.29 | v26.29,22.1 26.16,22.23 26.16,22.48 26.04,22.61 26.04,23.89 26.42,24.27 26.42,29.21 25.4,30.23 | v25.91,41.78 26.54,41.78 27.3,42.55
  Bottom 0.762: LCD_LIME.17 LCD_LIME2.17 27.3,42.55
  Bottom 1.016: 25.4,30.23 LCD_CON.17 25.4,34.92 25.78,35.31 v25.78,35.94
RXE1-  (via drill 0.5, 0.6)
  Top 0.508: v26.8,10.67 26.54,10.92 26.54,19.28 25.4,20.42 25.4,21.72 25.15,21.97 v25.15,22.1 | v24.51,36.07 24.89,36.45 24.89,42.8 27.05,44.96 27.05,46.23 27.56,46.74 v27.56,48.39
  Bottom 0.254: LCD.23 26.66,8.73 | 26.66,8.73 26.8,8.87 26.8,9.02 | 26.79,9.03 26.8,9.03 26.8,9.02 | 26.66,8.73 26.66,9.02 26.8,9.02
  Bottom 0.508: 26.79,9.03 26.92,9.17 26.92,10.54 v26.8,10.67 | v25.15,22.1 25.15,22.35 25.4,22.61 25.4,24.51 | 25.4,28.7 24.38,29.72 24.38,35.94 v24.51,36.07 25.53,37.08 25.91,37.08 27.3,38.48 | v27.56,48.39 27.3,48.64 27.3,49.78
  Bottom 0.762: 27.3,38.48 LCD_LIME2.18 | 27.3,49.78 LCD_LIME.18
  Bottom 1.016: 25.4,24.51 LCD_CON.18 25.4,28.7
RXE2+  (via drill 0.5, 0.6)
  Top 0.508: v29.59,9.02 29.59,9.65 29.34,9.91 29.34,11.81 28.7,12.45 28.7,23.62 v28.96,23.88 | v27.94,35.69 27.94,37.08 27.56,37.47 27.56,43.28 28.57,44.3 28.57,44.7 v28.96,45.09
  Bottom 0.254: LCD.27 28.66,8.29 | 28.66,8.29 28.66,8.47 28.83,8.64 28.96,8.64 28.96,8.58 28.66,8.29
  Bottom 0.508: 28.96,8.64 29.34,9.02 v29.59,9.02 | 27.94,30.35 28.96,29.34 v28.96,23.88
  Bottom 0.762: 28.57,45.09 LCD_LIME.19 | v28.96,45.09 28.57,45.09 | 28.57,45.09 LCD_LIME2.19
  Bottom 1.016: 27.94,30.35 LCD_CON.19 v27.94,35.69
RXE2-  (via drill 0.5, 0.6)
  Top 0.508: v28.55,9.5 28.7,9.65 28.7,11.53 28.07,12.17 28.07,23.62 v27.81,23.88 | v26.92,36.58 26.92,43.56 27.94,44.58 27.94,45.47 28.57,46.1 v28.57,49.4
  Bottom 0.254: 28.16,8.6 28.16,8.86 28.32,9.02 28.32,8.76 28.16,8.6 | LCD.26 28.16,8.6
  Bottom 0.508: 28.32,9.02 28.32,9.27 v28.55,9.5 | 27.94,28.83 26.92,29.84 v26.92,36.58 28.57,38.23
  Bottom 0.762: v27.81,23.88 27.94,24 LCD_CON.20 | 28.57,38.23 LCD_LIME2.20 | v28.57,49.4 LCD_LIME.20
  Bottom 1.016: LCD_CON.20 27.94,28.83
RXEC+  (via drill 0.5, 0.6)
  Top 0.508: v30.25,6.1 30,6.35 28.96,6.35 27.81,5.21 25.65,5.21 24.13,6.73 24.13,14.49 21.08,17.54 21.08,18.17 21.34,18.43 v21.34,18.54 | v10.16,35.56 10.16,36.3 12.34,38.48 13.74,38.48 15.62,40.36 15.62,41.27 v16,41.66
  Bottom 0.254: LCD.30 30.16,6.19 v30.25,6.1 | v16,41.66 16.51,42.16 19.3,42.16 19.68,42.55
  Bottom 0.508: 10.16,30.48 11.18,29.46 11.18,24.62 11.8,24 20.19,24 21.08,23.11 21.08,19.05 21.34,18.8 v21.34,18.54
  Bottom 0.762: LCD_LIME.5 LCD_LIME2.5 19.68,42.55
  Bottom 1.016: 10.16,30.48 LCD_CON.5 v10.16,35.56
RXEC-  (via drill 0.5, 0.6)
  Top 0.508: v29.34,5.44 29.31,5.46 29.08,5.46 28.19,4.57 25.39,4.57 23.5,6.46 23.5,14.22 20.45,17.27 20.45,18.16 20.19,18.41 v20.19,18.54 | v19.56,49.53 19.3,49.53 18.67,48.9 18.67,46.74 14.99,43.05 14.99,40.77 | v8.89,35.56 8.89,35.94 12.06,39.12 13.46,39.12 14.99,40.64 14.99,40.77 | 14.99,40.77 v14.61,40.77
  Bottom 0.254: 29.34,6.3 29.66,6.62 29.66,6.69 | 29.66,6.69 LCD.29 | 29.66,6.69 29.34,6.37 29.34,6.22 | 19.68,40.26 19.3,40.64 14.73,40.64 v14.61,40.77
  Bottom 0.508: v29.34,5.44 29.34,6.22 29.34,6.3 | 10.16,24.74 11.53,23.37 19.93,23.37 20.45,22.85 20.45,19.05 20.19,18.8 v20.19,18.54 | 10.16,28.96 9.14,29.97 9.14,35.31 v8.89,35.56
  Bottom 0.762: 19.68,40.26 LCD_LIME2.6 | v19.56,49.53 19.68,49.66 LCD_LIME.6
  Bottom 1.016: 10.16,24.74 LCD_CON.6 10.16,28.96
VCC  (via drill 0.6, 0.8)
  Top 1.27: 32.13,2.92 35.56,2.92 41.66,9.02 v44.2,9.02 | 32.13,2.92 32.13,7.87 31.75,8.26 31.75,9.78 34.54,12.57 v34.54,16.51 | v19.56,14.99 19.56,7.87 24.51,2.92 32.13,2.92
  Bottom 0.254: LCD.2 16.16,8.79 16.26,8.89 | LCD.3 16.66,8.74 16.51,8.89 | LCD.4 17.16,8.37 16.64,8.89
  Bottom 0.508: 34.04,16 BKL_E.2 | 44.58,7.24 3.3V/5.0V.1
  Bottom 1.016: v34.54,16.51 34.04,16 | 16.64,8.89 16.51,8.89 16.26,8.89 15.49,8.89 C2.1 C1.1 15.11,11.94 16.26,13.08 R7.1 R9.1 18.16,14.99 | R2.1 R1.2 18.16,16 18.16,14.99 | FET2.3 45.3,9.02 44.58,9.02 44.58,7.24 | 18.16,14.99 v19.56,14.99
  Bottom 1.27: 44.58,9.02 v44.2,9.02 v43.31,9.02
VLED_EN  (via drill 0.5, 0.6)
  Top 0.254: v18.92,3.68 17.78,4.83 17.27,4.83 15.75,6.35 15.75,10.67 17.14,12.06 v17.14,20.19 17.27,20.32 17.27,22.61 19.05,24.38 v19.05,25.27 | v23.75,48.26 23.75,47.12 20.7,44.07 20.7,38.48 v17.78,35.56
  Bottom 0.254: LCD.36 33.16,6.36 30.86,4.06 19.3,4.06 v18.92,3.68
  Bottom 0.508: v19.05,25.27 19.05,29.29 17.78,30.56
  Bottom 0.762: LCD_LIME2.11 LCD_LIME.11 23.5,48.01 v23.75,48.26
  Bottom 1.016: 17.78,30.56 LCD_CON.11 v17.78,35.56 | v17.14,20.19 17.14,19.05 R1.1
VPWM_EN  (via drill 0.6)
  Top 0.254: v17.4,3.94 17.27,3.94 15.24,5.97 15.24,10.92 15.88,11.56 v15.88,20.19 16.64,20.95 v16.64,25.27 | v23.5,49.53 22.86,48.9 22.86,46.99 20.19,44.32 20.19,39.24 v16.51,35.56
  Bottom 0.254: LCD.35 32.66,6.62 30.61,4.57 18.03,4.57 v17.4,3.94 | 17.78,29.08 16.51,30.35 v16.51,35.56 17.91,36.96 22.1,36.96 23.5,38.35
  Bottom 0.762: 23.5,38.35 LCD_LIME2.12 | v23.5,49.53 LCD_LIME.12
  Bottom 1.016: v16.64,25.27 17.78,25.27 LCD_CON.12 17.78,29.08 | v15.88,20.19 15.49,19.81 R2.2

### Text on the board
Top: Platkata trqbva da e debela 1mm!!!
Bottom: 56 errors
tNames: Platkata trqbva da e debela 1mm!!!
bNames: 39 | 1 | 2 | 5V_LCD_CON | https://www.olimex.com | PWR_JACK | LCD-OLinuXino-15.6FHD | Rev.E | 5V only | (C) 2014 | 10V_DC | JACK | PWR | JACK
